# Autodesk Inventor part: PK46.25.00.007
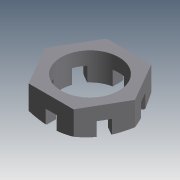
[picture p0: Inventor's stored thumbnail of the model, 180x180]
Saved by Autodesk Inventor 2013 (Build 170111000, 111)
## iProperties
Shininess: 25.0
Length Units: 11269
Angle Units: 11279
Time Units: 11290
Mass Units: 11283
Length Display Precision: 3
Angle Display Precision: 2
Created: 2001-04
Part Number: PK46.25.00.007
Material: Steel, Mild
Document SubType Name: Modeling
Designer: tevgeniy
Density: 7.86 g/cm^3
Density: 0.0
Volumn: 0.0
Area: 0.0
PropertySet Name: Model Information
Control State: 0
Master: False
Checked Out: True
Checked Out Date: 2008-10-15
Last Check In Date: 2008-10-15
Author: tevgeniy
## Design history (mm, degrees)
node "ExtrusionBlind1" dims "d6" = 25, "d7" = 0
  sketch "Sketch1"
    geometry: L1 (514.989, 469.325)-(474.575, 469.325); L2 (535.196, 434.325)-(514.989, 469.325); L3 (514.989, 399.325)-(535.196, 434.325); L4 (474.575, 399.325)-(514.989, 399.325); L5 (454.367, 434.325)-(474.575, 399.325); L6 (474.575, 469.325)-(454.367, 434.325); C1 r 35 at (494.782, 434.325)
    constraints: 12 end point, 6 tangent, 3 parallel, 1 centre point, 1 horizontal, 1 other
    dimensions: "d1" = 120 deg angle of L1 L2; "d3" = 120 deg angle of L5 L6; "d5" = 70 diameter of C1; "d29" = 70 distance between parallel lines of L1 L4 (derived)
node "ExtrusionThru1" dims "d14" = 0.13, "d15" = 0
  sketch "Sketch2"
    geometry: L1 (-476.374, -396.209)-(-475.874, -397.075); L2 (-503.696, -391.412)-(-503.261, -390.917); L3 (-516.411, -401.787)-(-515.911, -400.921); L4 (-514.989, -469.325)-(-535.196, -434.325) reference; L5 (-474.575, -469.325)-(-514.989, -469.325) reference; L6 (-454.367, -434.325)-(-474.575, -469.325) reference; L7 (-474.575, -399.325)-(-454.367, -434.325) reference; L8 (-514.989, -399.325)-(-474.575, -399.325) reference; L9 (-535.196, -434.325)-(-514.989, -399.325) reference; C1 r 26 at (-494.782, -434.325); C2 r 35 at (-494.782, -434.325)
    constraints: 6 end point, 6 tangent, 2 centre point, 1 coincident
    dimensions: "d13" = 52 diameter of C1
node "WorkAxis1"
node "WorkPlane1"
node "RevolutionFull1" dims "d24" = 360 deg
  sketch "Sketch3"
    geometry: L1 (0, 0)-(0, 25); L2 (34, 0)-(0, 0); L3 (40.415, 3.703)-(34, 0); L4 (40.415, 21.297)-(40.415, 3.703); L5 (34, 25)-(40.415, 21.297); L6 (0, 25)-(34, 25); L7 (0, 25)-(0.223, 25); L8 (-27.612, 0)-(-28.612, 0); L9 (40.415, 2.43)-(40.415, 1.43); L10 (0, 15.645)-(0, -15.645); L11 (0, 15.645)-(0, -15.645); L12 (20.207, 25)-(-20.207, 25) reference; L13 (-20.207, 0)-(20.207, 0) reference; L14 (0, -23.774)-(0, 33.129) reference; L15 (40.415, 25)-(40.415, 0) reference; L16 (34, 25)-(40.415, 25); L17 (40.415, 21.297)-(40.415, 25)
    constraints: 26 end point, 8 collinear, 3 horizontal, 3 vertical
    dimensions: "d17" = 34 distance of L1.end L5.start; "d19" = 30 deg angle of L6 L5; "d21" = 30 deg angle of L3 L2; "d23" = 0 horizontal distance of L5.start L2.start
sketch "Эскиз4"
  geometry: L1 (13.793, -3.703)-(-54.207, -3.703) reference; L2 (-25.207, -3.703)-(-15.207, -3.703); L3 (-15.207, -3.703)-(-15.207, 9.297); L4 (-15.207, 9.297)-(-25.207, 9.297); L5 (-25.207, 9.297)-(-25.207, -3.703); L6 (-20.207, -11.259)-(-20.207, 26.723) reference; L7 (0, 21.297)-(-40.415, 21.297) reference
  constraints: 8 end point, 2 parallel, 1 horizontal, 1 perpendicular, 1 point on line
  dimensions: "d32" = 10 distance of L3.end L4.end; "d33" = 5 distance between parallel lines of L5 L6 (= 0.5 x d32); "d39" = 12 distance between parallel lines of L4 L7
extrude "Выдавливание3" cut sketch "Эскиз4" stored distance "d34" = 10; taper "d35" = 0 deg
pattern_circular "Круговой массив1" dims angle "d38" = 360 deg
body "Solid1"
node "Спроецированная петля1"
other parameters: "d0" = 120 deg (derived), "d2" = 120 deg (derived), "d4" = 19 (derived), "d8" = 0, "d9" = 0, "d10" = 0, "d11" = 0, "d12" = 12 (derived), "d16" = 9 (derived), "d18" = 30 deg (derived), "d20" = 30 deg (derived), "d22" = 0 (derived)
